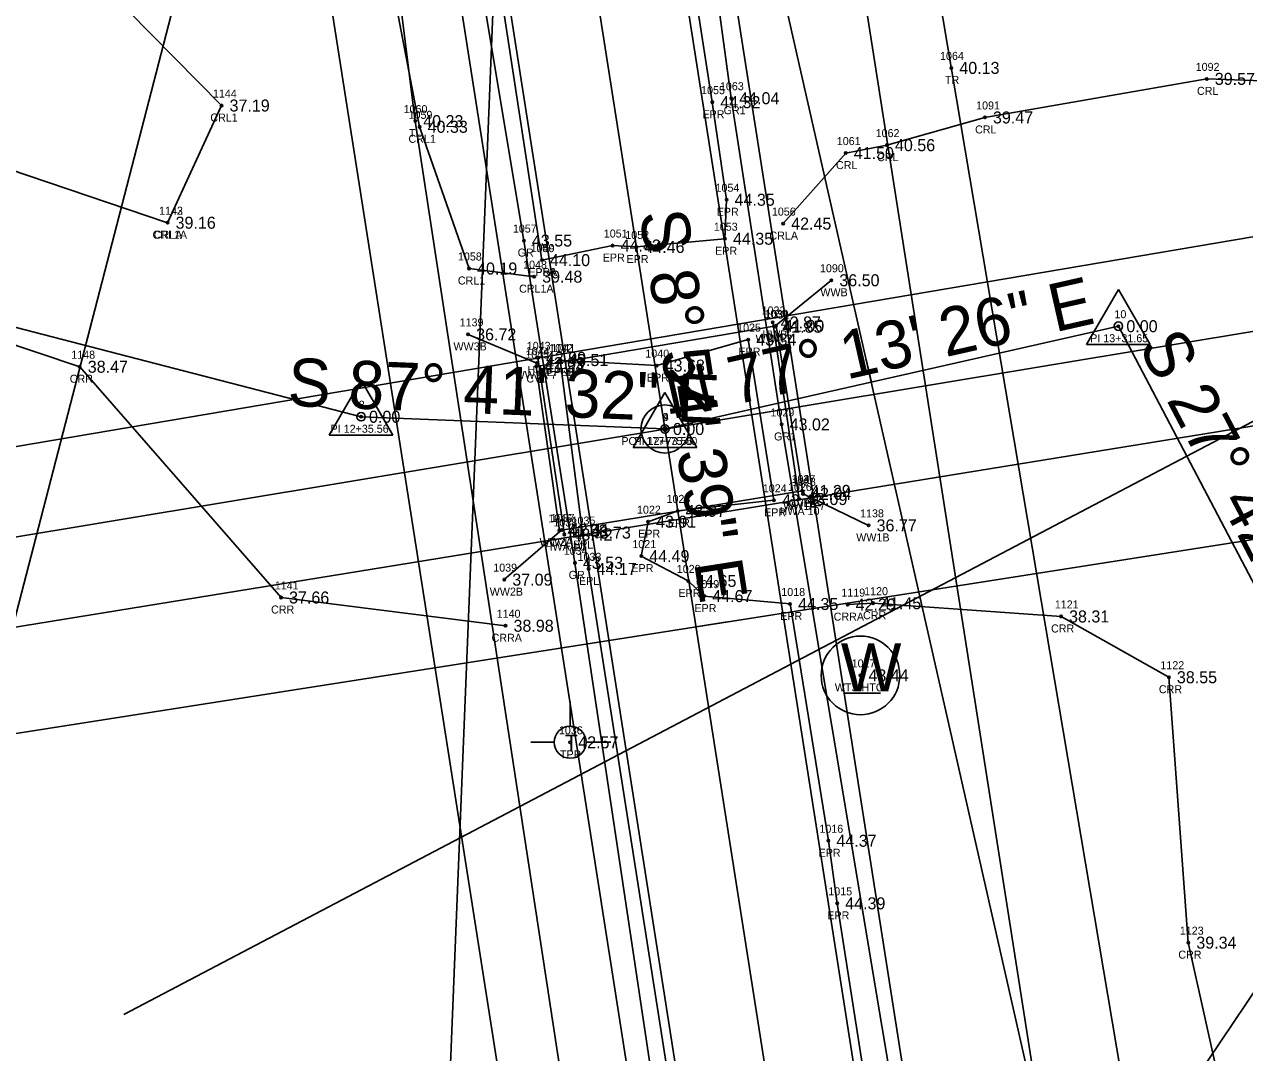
# Model space of a CAD drawing. Extents: x 2619568 to 2620316, y 784340 to 785138.
# Drawn here: x 2619755.9 to 2619908.4, y 784746.5 to 784874.9 of the extents above; entities that cross this region are included whole.
import ezdxf

# ---------------------------------------------------------------- set-up
doc = ezdxf.new("R2010")
doc.units = 0
for name, color, linetype in [('RD_EX_Bridge', 7, 'Continuous'), ('RD_EX_Bridge_txCode', 7, 'Continuous'), ('RD_EX_GuardRail', 7, 'Continuous'), ('RD_EX_GuardRail_txCode', 7, 'Continuous'), ('RD_EX_H2O', 7, 'Continuous'), ('RD_EX_H2O_txCode', 7, 'Continuous'), ('RD_EX_Road', 7, 'Continuous'), ('RD_EX_Road_txCode', 7, 'Continuous'), ('RD_EX_RW', 7, 'Continuous'), ('RD_EX_TX_Bridge_ELEV', 7, 'Continuous'), ('RD_EX_TX_GuardRail_ELEV', 7, 'Continuous'), ('RD_EX_TX_H2O_ELEV', 7, 'Continuous'), ('RD_EX_TX_Road_ELEV', 7, 'Continuous'), ('RD_EX_TX_UT_ELEV', 7, 'Continuous'), ('RD_EX_TX_VEG_ELEV', 7, 'Continuous'), ('RD_EX_UT', 7, 'Continuous'), ('RD_EX_UT_txCode', 7, 'Continuous'), ('RD_EX_VEG', 7, 'Continuous'), ('RD_EX_VEG_txCode', 7, 'Continuous'), ('RD_HC_Cl', 7, 'Continuous'), ('RD_HC_Data', 7, 'Continuous'), ('RD_HC_Data_Tic', 7, 'Continuous'), ('RD_HC_Survey_ELEV', 7, 'Continuous'), ('RD_HC_txCode', 7, 'Continuous'), ('RD_PD_Final_TrvlWay', 7, 'Continuous'), ('RD_PD_GR', 7, 'Continuous'), ('RD_PD_PatLn1', 7, 'Continuous'), ('RD_PD_PatLn2', 7, 'Continuous'), ('RD_PD_PatLn3', 7, 'Continuous'), ('RD_SMD_Locator', 7, 'Continuous')]:
    doc.layers.add(name, color=color, linetype=linetype)

msp = doc.modelspace()

# ---------------------------------------------------------------- linework, layer by layer
at = {"layer": 'RD_EX_Bridge'}
for p, q in [((2619849.63, 784837.16), (2619856.76, 784842.96)), ((2619852.74, 784815.63), (2619849.44, 784837.69)), ((2619819.97, 784832.61), (2619811.38, 784836.2)), ((2619823.41, 784811.2), (2619820.1, 784833.27)), ((2619853.23, 784816.28), (2619861.41, 784812.34)), ((2619823.08, 784811.77), (2619815.9, 784805.56))]:
    msp.add_line(p, q, dxfattribs=at)
msp.add_lwpolyline([(2619853.16, 784816.64), (2619849.85, 784837.27), (2619819.89, 784832.19), (2619822.79, 784811.7), (2619853.16, 784816.64)], dxfattribs=at)
at = {"layer": 'RD_EX_GuardRail'}
for points in [[(2619867.12, 784523.3), (2619850.86, 784633.15), (2619824.72, 784807.66), (2619818.35, 784847.92), (2619803.75, 784935.38), (2619787.81, 785031.17), (2619775.16, 785106.97)], [(2619898.96, 784529.78), (2619881.94, 784636.77), (2619850.55, 784824.95), (2619844.25, 784865.7), (2619839.24, 784902.52)]]:
    msp.add_lwpolyline(points, dxfattribs=at)
at = {"layer": 'RD_EX_H2O'}
for points in [[(2619819.63, 784843.41), (2619811.5, 784844.43), (2619805.32, 784862.13), (2619791.73, 784933.03)], [(2619773.83, 784850.15), (2619780.57, 784864.79), (2619733.81, 784912.21), (2619700.27, 784924.63), (2619672.07, 784923.77), (2619649.36, 784903.37), (2619624.57, 784890.48)], [(2619773.83, 784850.15), (2619738.99, 784861.9), (2619696.47, 784872.3), (2619650.86, 784880.63), (2619624.57, 784890.48)], [(2619850.74, 784850.04), (2619858.56, 784858.85), (2619863.71, 784859.84), (2619875.95, 784863.3), (2619903.67, 784868.12), (2619924.46, 784867.36), (2619949.26, 784874.61), (2619971.3, 784850.55), (2619990.94, 784832.2), (2619978.09, 784805.14), (2619980.54, 784803.04), (2620013.79, 784776.16)], [(2619816.05, 784799.8), (2619788.01, 784803.33), (2619762.86, 784832.16), (2619731.33, 784842.74), (2619695.49, 784847.41), (2619650.29, 784835.61), (2619600.27, 784824.84)], [(2619858.79, 784802.44), (2619861.97, 784802.62), (2619885.46, 784800.96), (2619898.93, 784793.37), (2619901.36, 784760.21), (2619910.66, 784718.33), (2619929.66, 784699.53), (2619944.47, 784658), (2619963.48, 784625.35)]]:
    msp.add_lwpolyline(points, dxfattribs=at)
at = {"layer": 'RD_EX_Road'}
for p, q in [((2619841.88, 784865.21), (2619830.54, 784938.02)), ((2619820.6, 784845.48), (2619806.71, 784935.63)), ((2619843.67, 784853.02), (2619841.88, 784865.21)), ((2619843.47, 784848.15), (2619843.67, 784853.02)), ((2619820.6, 784845.48), (2619829.43, 784847.3)), ((2619829.43, 784847.3), (2619832.4, 784847.12)), ((2619832.4, 784847.12), (2619843.47, 784848.15)), ((2619846.37, 784835.55), (2619834.94, 784832.3)), ((2619849.59, 784815.47), (2619846.37, 784835.55)), ((2619834.94, 784832.3), (2619822.88, 784832.99)), ((2619825.69, 784811.44), (2619822.88, 784832.99)), ((2619837.56, 784814.15), (2619849.59, 784815.47)), ((2619833.86, 784812.8), (2619837.56, 784814.15)), ((2619833.01, 784808.5), (2619833.86, 784812.8)), ((2619826.43, 784806.91), (2619825.69, 784811.44)), ((2619838.88, 784805.4), (2619833.01, 784808.5)), ((2619837.85, 784734.18), (2619826.43, 784806.91)), ((2619840.88, 784803.5), (2619838.88, 784805.4)), ((2619851.61, 784802.52), (2619840.88, 784803.5)), ((2619856.39, 784772.94), (2619851.61, 784802.52)), ((2619857.49, 784765.12), (2619856.39, 784772.94)), ((2619862.04, 784735.87), (2619857.49, 784765.12))]:
    msp.add_line(p, q, dxfattribs=at)
at = {"layer": 'RD_EX_RW'}
for p, q in [((2619822.1, 785125.87), (2619915.04, 784533.11)), ((2619756.9, 785115.64), (2619849.84, 784522.89))]:
    msp.add_line(p, q, dxfattribs=at)
at = {"layer": 'RD_EX_UT'}
for p, q in [((2619858.28, 784791.39), (2619862.91, 784791.39)), ((2619824.13, 784790.31), (2619824.13, 784787.24)), ((2619819.2, 784785.26), (2619822.13, 784785.26)), ((2619826.13, 784785.26), (2619829.2, 784785.26))]:
    msp.add_line(p, q, dxfattribs=at)
for centre, radius in [((2619860.4, 784793.6), 4.91), ((2619824.13, 784785.24), 2)]:
    msp.add_circle(centre, radius, dxfattribs=at)
at = {"layer": 'RD_EX_VEG'}
for points in [[(2619930.82, 784519.47), (2619827.3, 785132.88)], [(2619857.01, 784520.73), (2619804.77, 784862.84), (2619772.02, 785124.21)]]:
    msp.add_lwpolyline(points, dxfattribs=at)
at = {"layer": 'RD_HC_Cl'}
for p, q in [((2619789.5, 785120.76), (2619882.44, 784528)), ((2619614.33, 784873.47), (2619798, 784825.91)), ((2619835.97, 784824.38), (2619892.62, 784837.22)), ((2619892.62, 784837.22), (2619923.2, 784779.01)), ((2619798, 784825.91), (2619835.97, 784824.38))]:
    msp.add_line(p, q, dxfattribs=at)
at = {"layer": 'RD_HC_Data'}
for p, q in [((2619888.65, 784834.93), (2619892.62, 784841.81)), ((2619892.62, 784841.81), (2619896.59, 784834.93)), ((2619888.65, 784834.93), (2619896.59, 784834.93)), ((2619794.03, 784823.61), (2619798, 784830.49)), ((2619798, 784830.49), (2619801.97, 784823.61)), ((2619832, 784822.08), (2619835.97, 784828.96)), ((2619835.97, 784828.96), (2619839.94, 784822.08)), ((2619794.03, 784823.61), (2619801.97, 784823.61)), ((2619832, 784822.08), (2619839.94, 784822.08))]:
    msp.add_line(p, q, dxfattribs=at)
for centre, radius in [((2619892.62, 784837.22), 0.529), ((2619835.97, 784824.38), 3), ((2619798, 784825.91), 0.529), ((2619835.97, 784824.38), 0.529), ((2619835.97, 784824.38), 0.282)]:
    msp.add_circle(centre, radius, dxfattribs=at)
at = {"layer": 'RD_HC_Data_Tic'}
for p, q in [((2619763.58, 784834.82), (2619764.58, 784838.69)), ((2619861.76, 784830.22), (2619860.87, 784834.12)), ((2619839.84, 784799.68), (2619843.79, 784800.3))]:
    msp.add_line(p, q, dxfattribs=at)
at = {"layer": 'RD_PD_Final_TrvlWay'}
for p, q in [((2619804.24, 785097.76), (2619881.69, 784603.8)), ((2619782.51, 785094.35), (2619859.95, 784600.39))]:
    msp.add_line(p, q, dxfattribs=at)
at = {"layer": 'RD_PD_GR'}
for p, q in [((2619851.12, 784617.98), (2619784.32, 785044.03)), ((2619845.02, 784876.41), (2619879.87, 784654.12))]:
    msp.add_line(p, q, dxfattribs=at)
at = {"layer": 'RD_PD_PatLn1'}
msp.add_line((2619988.03, 784822.91), (2619691.65, 784776.44), dxfattribs=at)
at = {"layer": 'RD_PD_PatLn2'}
for p, q in [((2619801.18, 784980.03), (2619725.97, 784689.61)), ((2619828.58, 784976.51), (2619894.93, 784683.94)), ((2619818.47, 784975.2), (2619806.39, 784675.45)), ((2620008.98, 784902.09), (2619841.72, 784653.04)), ((2620033.95, 784890.73), (2619768.36, 784751.23))]:
    msp.add_line(p, q, dxfattribs=at)
at = {"layer": 'RD_PD_PatLn3'}
for p, q in [((2619686.31, 784810.54), (2619982.1, 784860.72)), ((2619687.99, 784799.79), (2619983.95, 784848.95)), ((2619689.68, 784789.04), (2619985.79, 784837.19))]:
    msp.add_line(p, q, dxfattribs=at)
at = {"layer": 'RD_SMD_Locator'}
for centre in [(2619871.75, 784869.49), (2619903.67, 784868.12), (2619844.25, 784865.7), (2619780.57, 784864.79), (2619841.88, 784865.21), (2619804.77, 784862.84), (2619875.95, 784863.3), (2619805.32, 784862.13), (2619863.71, 784859.84), (2619858.56, 784858.85), (2619843.67, 784853.02), (2619773.83, 784850.15), (2619773.83, 784850.15), (2619850.74, 784850.04), (2619818.35, 784847.92), (2619829.43, 784847.3), (2619832.4, 784847.12), (2619843.47, 784848.15), (2619811.5, 784844.43), (2619820.6, 784845.48), (2619820.6, 784845.48), (2619819.63, 784843.41), (2619856.76, 784842.96), (2619849.44, 784837.69), (2619849.63, 784837.16), (2619849.85, 784837.27), (2619892.62, 784837.22), (2619811.38, 784836.2), (2619846.37, 784835.55), (2619762.86, 784832.16), (2619819.89, 784832.19), (2619819.97, 784832.61), (2619820.1, 784833.27), (2619822.88, 784832.99), (2619822.88, 784832.99), (2619834.94, 784832.3), (2619798, 784825.91), (2619835.97, 784824.38), (2619835.97, 784824.38), (2619850.55, 784824.95), (2619853.16, 784816.64), (2619853.16, 784816.64), (2619849.59, 784815.47), (2619852.74, 784815.63), (2619853.23, 784816.28), (2619837.56, 784814.15), (2619833.86, 784812.8), (2619861.41, 784812.34), (2619822.79, 784811.7), (2619823.08, 784811.77), (2619823.41, 784811.2), (2619825.69, 784811.44), (2619824.72, 784807.66), (2619833.01, 784808.5), (2619826.43, 784806.91), (2619815.9, 784805.56), (2619838.88, 784805.4), (2619788.01, 784803.33), (2619840.88, 784803.5), (2619851.61, 784802.52), (2619858.79, 784802.44), (2619861.97, 784802.62), (2619816.05, 784799.8), (2619885.46, 784800.96), (2619860.4, 784793.6), (2619898.93, 784793.37), (2619824.13, 784785.24), (2619856.39, 784772.94), (2619857.49, 784765.12), (2619901.36, 784760.21)]:
    msp.add_circle(centre, 0.15, dxfattribs=at)

# ---------------------------------------------------------------- texts
at = {"layer": 'RD_EX_Bridge_txCode'}
for s, p in [('1090', (2619855.34, 784843.96)), ('WWB', (2619855.39, 784840.96)), ('1032', (2619848.05, 784838.69)), ('1139', (2619810.32, 784837.2)), ('1030', (2619848.42, 784838.27)), ('1031', (2619848.53, 784838.16)), ('HWB', (2619848.15, 784835.69)), ('WW3B', (2619809.55, 784834.2)), ('1043', (2619818.71, 784834.27)), ('WWA 7', (2619847.3, 784835.16)), ('CVL', (2619848.6, 784835.27)), ('1045', (2619818.51, 784833.19)), ('1044', (2619818.59, 784833.61)), ('HWB', (2619818.81, 784831.27)), ('WW3A 7', (2619817.19, 784830.61)), ('CVL', (2619818.65, 784830.19)), ('1027', (2619851.78, 784817.64)), ('1047', (2619851.78, 784817.64)), ('1028', (2619851.85, 784817.28)), ('1026', (2619851.34, 784816.63)), ('WW1A 7', (2619850.74, 784814.28)), ('CVLA', (2619851.43, 784814.64)), ('CVLB', (2619851.45, 784814.64)), ('1046', (2619821.38, 784812.7)), ('1037', (2619821.7, 784812.77)), ('HWA 10', (2619850.3, 784813.63)), ('1138', (2619860.35, 784813.34)), ('1038', (2619822.03, 784812.2)), ('WW2A 7', (2619820.3, 784809.77)), ('CVL', (2619821.55, 784809.7)), ('WW1B', (2619859.87, 784810.34)), ('HWA 10', (2619820.96, 784809.2)), ('1039', (2619814.52, 784806.56)), ('WW2B', (2619814.08, 784803.56))]:
    msp.add_text(s, height=1, dxfattribs=at).set_placement(p)
at = {"layer": 'RD_EX_GuardRail_txCode'}
for s, p in [('1063', (2619842.84, 784866.7)), ('GR1', (2619843.3, 784863.7)), ('1057', (2619816.97, 784848.92)), ('GR', (2619817.57, 784845.92)), ('1029', (2619849.16, 784825.95)), ('GR1', (2619849.6, 784822.95)), ('1034', (2619823.33, 784808.66)), ('GR', (2619823.94, 784805.66))]:
    msp.add_text(s, height=1, dxfattribs=at).set_placement(p)
at = {"layer": 'RD_EX_H2O_txCode'}
for s, p in [('1092', (2619902.28, 784869.12)), ('CRL', (2619902.44, 784866.12)), ('1144', (2619779.5, 784865.79)), ('1059', (2619803.94, 784863.13)), ('1091', (2619874.85, 784864.3)), ('CRL1', (2619779.17, 784862.79)), ('CRL1', (2619803.93, 784860.13)), ('1062', (2619862.3, 784860.84)), ('CRL', (2619874.72, 784861.3)), ('1061', (2619857.44, 784859.85)), ('CRL', (2619857.34, 784856.85)), ('CRL', (2619862.48, 784857.84)), ('1142', (2619772.77, 784851.15)), ('1143', (2619772.77, 784851.15)), ('1056', (2619849.33, 784851.04)), ('CRL1A', (2619771.95, 784848.15)), ('CRLA', (2619772.11, 784848.15)), ('CRLA', (2619849.03, 784848.04)), ('1058', (2619810.11, 784845.43)), ('1048', (2619818.25, 784844.41)), ('CRL1', (2619810.1, 784842.43)), ('CRL1A', (2619817.75, 784841.41)), ('1148', (2619761.8, 784833.16)), ('CRR', (2619761.61, 784830.16)), ('1141', (2619787.23, 784804.33)), ('1120', (2619860.86, 784803.62)), ('1119', (2619858.01, 784803.44)), ('CRR', (2619786.76, 784801.33)), ('1140', (2619814.95, 784800.8)), ('CRRA', (2619857.05, 784800.44)), ('CRR', (2619860.72, 784800.62)), ('1121', (2619884.68, 784801.96)), ('CRR', (2619884.21, 784798.96)), ('CRRA', (2619814.31, 784797.8)), ('1122', (2619897.87, 784794.37)), ('CRR', (2619897.68, 784791.37)), ('1123', (2619900.3, 784761.21)), ('CRR', (2619900.11, 784758.21))]:
    msp.add_text(s, height=1, dxfattribs=at).set_placement(p)
at = {"layer": 'RD_EX_Road_txCode'}
for s, p in [('1055', (2619840.49, 784866.21)), ('EPR', (2619840.65, 784863.21)), ('1054', (2619842.29, 784854.02)), ('EPR', (2619842.44, 784851.02)), ('1051', (2619828.33, 784848.3)), ('1052', (2619831.02, 784848.12)), ('1053', (2619842.08, 784849.15)), ('1050', (2619819.17, 784846.48)), ('1049', (2619819.21, 784846.48)), ('EPR', (2619828.2, 784845.3)), ('EPR', (2619831.17, 784845.12)), ('EPR', (2619842.24, 784846.15)), ('EPRA', (2619818.88, 784843.48)), ('EPLA', (2619818.91, 784843.48)), ('1025', (2619844.99, 784836.55)), ('1042', (2619821.5, 784833.99)), ('1041', (2619821.78, 784833.99)), ('1040', (2619833.52, 784833.3)), ('EPR', (2619845.15, 784833.55)), ('EPRB', (2619821.18, 784830.99)), ('EPLB', (2619821.2, 784830.99)), ('EPR', (2619833.72, 784830.3)), ('1024', (2619848.2, 784816.47)), ('1023', (2619836.17, 784815.15)), ('1022', (2619832.48, 784813.8)), ('EPR', (2619848.36, 784813.47)), ('1035', (2619824.3, 784812.44)), ('EPR', (2619836.33, 784812.15)), ('EPR', (2619832.63, 784810.8)), ('EPL', (2619824.48, 784809.44)), ('1021', (2619831.9, 784809.5)), ('1033', (2619825.05, 784807.91)), ('EPR', (2619831.78, 784806.5)), ('1020', (2619837.45, 784806.4)), ('EPL', (2619825.23, 784804.91)), ('1019', (2619839.78, 784804.5)), ('1018', (2619850.51, 784803.52)), ('EPR', (2619837.65, 784803.4)), ('EPR', (2619839.65, 784801.5)), ('EPR', (2619850.38, 784800.52)), ('1016', (2619855.27, 784773.94)), ('EPR', (2619855.17, 784770.94)), ('1015', (2619856.38, 784766.12)), ('EPR', (2619856.26, 784763.12))]:
    msp.add_text(s, height=1, dxfattribs=at).set_placement(p)
at = {"layer": 'RD_EX_TX_Bridge_ELEV'}
for s, p in [('36.50', (2619857.76, 784842.21)), ('42.87', (2619850.44, 784836.94)), ('41.00', (2619850.85, 784836.52)), ('36.72', (2619812.38, 784835.45)), ('41.85', (2619850.63, 784836.41)), ('42.99', (2619821.1, 784832.52)), ('41.34', (2619820.89, 784831.44)), ('42.09', (2619820.97, 784831.86)), ('41.29', (2619854.16, 784815.89)), ('41.29', (2619854.16, 784815.89)), ('42.04', (2619854.23, 784815.53)), ('43.09', (2619853.74, 784814.88)), ('41.63', (2619823.79, 784810.95)), ('42.41', (2619824.08, 784811.02)), ('36.77', (2619862.41, 784811.59)), ('43.42', (2619824.41, 784810.45)), ('37.09', (2619816.9, 784804.81))]:
    msp.add_text(s, height=1.5, dxfattribs=at).set_placement(p)
at = {"layer": 'RD_EX_TX_GuardRail_ELEV'}
for s, p in [('44.04', (2619845.25, 784864.95)), ('43.55', (2619819.35, 784847.17)), ('43.02', (2619851.55, 784824.2)), ('43.53', (2619825.72, 784806.91))]:
    msp.add_text(s, height=1.5, dxfattribs=at).set_placement(p)
at = {"layer": 'RD_EX_TX_H2O_ELEV'}
for s, p in [('39.57', (2619904.67, 784867.37)), ('37.19', (2619781.57, 784864.04)), ('39.47', (2619876.95, 784862.55)), ('40.33', (2619806.32, 784861.38)), ('41.50', (2619859.56, 784858.1)), ('40.56', (2619864.71, 784859.09)), ('39.16', (2619774.83, 784849.4)), ('39.16', (2619774.83, 784849.4)), ('42.45', (2619851.74, 784849.29)), ('40.19', (2619812.5, 784843.68)), ('39.48', (2619820.63, 784842.66)), ('38.47', (2619763.86, 784831.41)), ('37.66', (2619789.01, 784802.58)), ('42.29', (2619859.79, 784801.69)), ('41.45', (2619862.97, 784801.87)), ('38.31', (2619886.46, 784800.21)), ('38.98', (2619817.05, 784799.05)), ('38.55', (2619899.93, 784792.62)), ('39.34', (2619902.36, 784759.46))]:
    msp.add_text(s, height=1.5, dxfattribs=at).set_placement(p)
at = {"layer": 'RD_EX_TX_Road_ELEV'}
for s, p in [('44.32', (2619842.88, 784864.46)), ('44.35', (2619844.67, 784852.27)), ('44.35', (2619844.47, 784847.4)), ('44.42', (2619830.43, 784846.55)), ('44.46', (2619833.4, 784846.37)), ('44.10', (2619821.6, 784844.73)), ('44.10', (2619821.6, 784844.73)), ('43.34', (2619847.37, 784834.8)), ('43.51', (2619823.88, 784832.24)), ('43.51', (2619823.88, 784832.24)), ('43.68', (2619835.94, 784831.55)), ('43.42', (2619850.59, 784814.72)), ('43.97', (2619838.56, 784813.4)), ('43.73', (2619826.69, 784810.69)), ('43.91', (2619834.86, 784812.05)), ('44.49', (2619834.01, 784807.75)), ('44.17', (2619827.43, 784806.16)), ('44.65', (2619839.88, 784804.65)), ('44.67', (2619841.88, 784802.75)), ('44.35', (2619852.61, 784801.77)), ('44.37', (2619857.39, 784772.19)), ('44.39', (2619858.49, 784764.37))]:
    msp.add_text(s, height=1.5, dxfattribs=at).set_placement(p)
at = {"layer": 'RD_EX_TX_UT_ELEV'}
for s, p in [('43.44', (2619861.4, 784792.85)), ('42.57', (2619825.13, 784784.49))]:
    msp.add_text(s, height=1.5, dxfattribs=at).set_placement(p)
at = {"layer": 'RD_EX_TX_VEG_ELEV'}
for s, p in [('40.13', (2619872.75, 784868.74)), ('40.23', (2619805.77, 784862.09))]:
    msp.add_text(s, height=1.5, dxfattribs=at).set_placement(p)
at = {"layer": 'RD_EX_UT'}
for s, height, p in [('W', 6, (2619857.94, 784791.6)), ('T', 2, (2619823.46, 784784.2))]:
    msp.add_text(s, height=height, dxfattribs=at).set_placement(p)
at = {"layer": 'RD_EX_UT_txCode'}
for s, p in [('1017', (2619859.3, 784794.6)), ('WTS HTC', (2619857.19, 784791.6)), ('1036', (2619822.72, 784786.24)), ('TPP', (2619822.86, 784783.24))]:
    msp.add_text(s, height=1, dxfattribs=at).set_placement(p)
at = {"layer": 'RD_EX_VEG_txCode'}
for s, p in [('1064', (2619870.34, 784870.49)), ('TR', (2619870.96, 784867.49)), ('1060', (2619803.32, 784863.84)), ('TL', (2619804, 784860.84))]:
    msp.add_text(s, height=1, dxfattribs=at).set_placement(p)
at = {"layer": 'RD_HC_Data'}
for s, rotation, p in [('S 8%%d 54\' 39" E', 278.9109, (2619832.75, 784851.34)), ('N 77%%d 13\' 26" E', 12.7761, (2619836.82, 784825.59)), ('S 27%%d 42\' 37" E', 297.7103, (2619895.05, 784834.74)), ('S 87%%d 41\' 32" E', 357.6921, (2619788.77, 784827.28))]:
    msp.add_text(s, height=6, rotation=rotation, dxfattribs=at).set_placement(p)
at = {"layer": 'RD_HC_Survey_ELEV'}
for p in [(2619893.62, 784836.47), (2619799, 784825.16), (2619836.97, 784823.63), (2619836.97, 784823.63)]:
    msp.add_text('0.00', height=1.5, dxfattribs=at).set_placement(p)
at = {"layer": 'RD_HC_txCode'}
for s, p in [('10', (2619892.13, 784838.22)), ('PI 13+31.65', (2619889.1, 784835.22)), ('8', (2619797.71, 784826.91)), ('4', (2619835.69, 784825.38)), ('9', (2619835.69, 784825.38)), ('PI 12+35.56', (2619794.2, 784823.91)), ('POT 177+75.00', (2619830.53, 784822.38)), ('PI 12+73.56', (2619832.17, 784822.38))]:
    msp.add_text(s, height=1, dxfattribs=at).set_placement(p)

doc.saveas('drawing.dxf')
